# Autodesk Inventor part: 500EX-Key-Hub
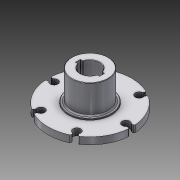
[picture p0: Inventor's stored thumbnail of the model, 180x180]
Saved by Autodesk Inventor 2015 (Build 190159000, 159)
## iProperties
Created: 2015-01
Part Number: 500EX-Key-Hub
Material: Aluminum 6061
Document SubType Name: Modeling
Designer: TODD D MILLER
Mass: 45.277 g
Surface Area: 81.3038 cm^2
Volume: 16.7693 cm^3
Density: 2.7 g/cm^3
Appearance: Aluminum - Flat
Author: Andy Baker
Title: 500EX-Key-Hub.STEP
Organization: AndyMark Inc.
Description: STEP AP203
Creation Date: 2012-01-06
Sending System: SolidWorks 2010
Preprocessor: SwSTEP 2.0
Author: TODD D MILLER
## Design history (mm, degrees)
node "500EX-Key-Hub1"
body "Solid5"
feature "Base1"
